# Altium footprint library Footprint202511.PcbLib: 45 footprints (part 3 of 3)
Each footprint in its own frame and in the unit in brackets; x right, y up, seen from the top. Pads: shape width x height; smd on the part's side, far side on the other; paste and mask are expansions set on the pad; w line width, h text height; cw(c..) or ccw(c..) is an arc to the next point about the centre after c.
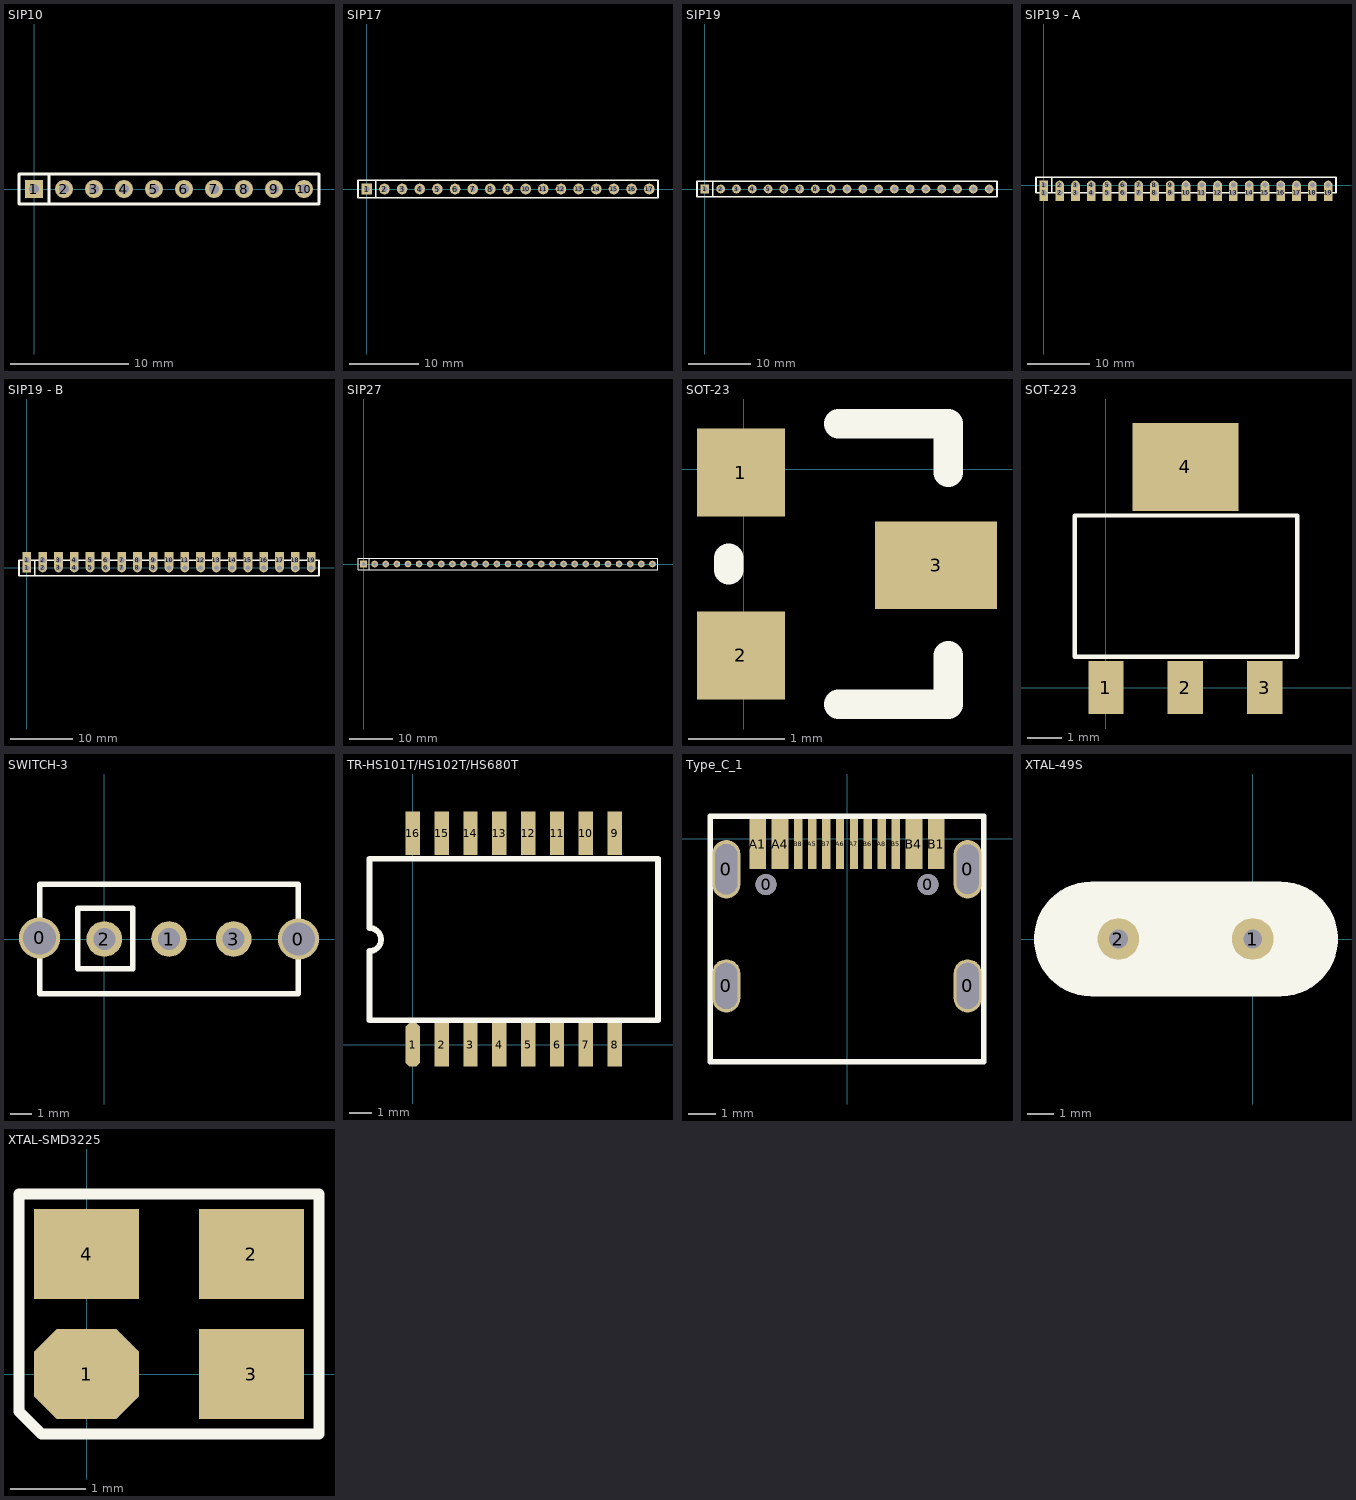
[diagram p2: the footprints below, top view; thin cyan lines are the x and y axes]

## SIP10 [mil]
pads (10):
  rect 60x60 hole 32: 1(0,0)
  round 60 hole 32: 2(100,0) 3(200,0) 4(300,0) 5(400,0) 6(500,0) 7(600,0) 8(700,0) 9(800,0) 10(900,0)
Top Overlay:
  lines w10: 50,-50 50,50 ; 950,-50 -50,-50 -50,50 950,50 950,-45

## SIP17 [mil]
height 43.31
pads (17):
  rect 60x60 hole 32: 1(0,0)
  round 60 hole 32: 2(100,0) 3(200,0) 4(300,0) 5(400,0) 6(500,0) 7(600,0) 8(700,0) 9(800,0) 10(900,0) 11(1000,0) 12(1100,0) 13(1200,0) 14(1300,0) 15(1400,0) 16(1500,0) 17(1600,0)
Top Overlay:
  lines w10: 50,-50 50,50 ; -50,-50 -50,50 1650,50 1650,-50 -50,-50

## SIP19 [mil]
height 43.31
pads (19):
  rect 55x55 hole 32: 1(0,0)
  round 55 hole 32: 2(100,0) 3(200,0) 4(300,0) 5(400,0) 6(500,0) 7(600,0) 8(700,0) 9(800,0) 10(900,0) 11(1000,0) 12(1100,0) 13(1200,0) 14(1300,0) 15(1400,0) 16(1500,0) 17(1600,0) 18(1700,0) 19(1800,0)
Top Overlay:
  lines w10: 50,-50 50,50 ; -50,-50 1850,-50 1850,50 -50,50 -50,-50

## SIP19 - A [mil]
height 43.31
pads (38):
  rect 55x100 hole 32: 1(0,-50) 2(100,-50) 3(200,-50)
  rect 55x55 hole 32: 1(0,0)
  round 55 hole 32: 2(100,0) 3(200,0) 4(300,0) 5(400,0) 6(500,0) 7(600,0) 8(700,0) 9(800,0) 10(900,0) 11(1000,0) 12(1100,0) 13(1200,0) 14(1300,0) 15(1400,0) 16(1500,0) 17(1600,0) 18(1700,0) 19(1800,0)
  rect 55x100 hole 32 unplated: 4(300,-50) 5(400,-50) 6(500,-50) 7(600,-50) 8(700,-50) 9(800,-50) 10(900,-50) 11(1000,-50) 12(1100,-50) 13(1200,-50) 14(1300,-50) 15(1400,-50) 16(1500,-50) 17(1600,-50) 18(1700,-50) 19(1800,-50)
Top Overlay:
  lines w10: 50,-50 50,50 ; -50,-50 -50,50 1850,50 1850,-50 -50,-50

## SIP19 - B [mil]
height 43.31
pads (38):
  rect 55x55 hole 32: 1(0,0)
  rect 55x100 hole 32: 1(0,50) 2(100,50) 3(200,50)
  round 55 hole 32: 2(100,0) 3(200,0) 4(300,0) 5(400,0) 6(500,0) 7(600,0) 8(700,0) 9(800,0) 10(900,0) 11(1000,0) 12(1100,0) 13(1200,0) 14(1300,0) 15(1400,0) 16(1500,0) 17(1600,0) 18(1700,0) 19(1800,0)
  rect 55x100 hole 32 unplated: 4(300,50) 5(400,50) 6(500,50) 7(600,50) 8(700,50) 9(800,50) 10(900,50) 11(1000,50) 12(1100,50) 13(1200,50) 14(1300,50) 15(1400,50) 16(1500,50) 17(1600,50) 18(1700,50) 19(1800,50)
Top Overlay:
  lines w10: 50,-50 50,50 ; -50,-50 -50,50 1850,50 1850,-50 -50,-50

## SIP27 [mil]
height 43.31
pads (27):
  rect 60x60 hole 32: 1(0,0)
  round 60 hole 32: 2(100,0) 3(200,0) 4(300,0) 5(400,0) 6(500,0) 7(600,0) 8(700,0) 9(800,0) 10(900,0) 11(1000,0) 12(1100,0) 13(1200,0) 14(1300,0) 15(1400,0) 16(1500,0) 17(1600,0) 18(1700,0) 19(1800,0) 20(1900,0) 21(2000,0) 22(2100,0) 23(2200,0) 24(2300,0) 25(2400,0) 26(2500,0) 27(2600,0)
Top Overlay:
  lines w10: 50,-50 50,50 ; -50,-50 2650,-50 2650,50 -50,50 -50,-50

## SOT-23 [mil]
height 43.31
pads (3):
  rect 36x36 smd: 1(-1.26,-1.37) 2(-1.26,-76.37)
  rect 50x36 smd: 3(78.74,-39.37)
Top Overlay:
  lines w12: -6.26,-41.37 -6.26,-36.37 ; 38.74,-96.37 83.74,-96.37 83.74,-76.37 ; 38.74,18.63 83.74,18.63 83.74,-1.37

## SOT-223 [mil]
height 43.31
pads (4):
  rect 40x60 smd: 1(0,0) 2(90,0) 3(180,0)
  rect 120x100 smd: 4(90,250)
Top Overlay:
  lines w5: -35.43,35 -35.43,194.57 -35,195 216.97,195 216.97,35.43 216.54,35 -35.43,35

## SWITCH-3 [mil]
height 21.65
pads (5):
  round 75 hole 60: 0(-118,2) 0(354,0)
  round 65 hole 40: 1(118,0) 2(0,0) 3(236,0)
Top Overlay:
  lines w10: -118,-100 -118,100 354,100 354,-100 -118,-100 ; -48,-54 -48,56 52,56 52,-54 -48,-54

## TR-HS101T/HS102T/HS680T [mm]
pads (16):
  oct 0.635x1.905 smd: 1(0,0)
  rect 0.635x1.905 smd: 2(1.27,0) 3(2.54,0) 4(3.81,0) 5(5.08,0) 6(6.35,0) 7(7.62,0) 8(8.89,0) 9(8.89,9.3) 10(7.62,9.3) 11(6.35,9.3) 12(5.08,9.3) 13(3.81,9.3) 14(2.54,9.3) 15(1.27,9.3) 16(0,9.3)
Top Overlay:
  lines w0.254: -1.905,1.07 -1.905,4.118 ccw(c-1.905,4.626) -1.905,5.134 -1.905,8.182 10.795,8.182 10.795,1.07 -1.905,1.07

## Type_C_1 [mm]
pads (18):
  oval 1x1.9 hole 0.8 slot 1.651 at 90 deg: 0(-4.325,-5.28) 0(4.325,-5.28)
  oval 1x2.1 hole 0.8 slot 1.803 at 90 deg: 0(-4.325,-1.1)
  round 0.75 hole 0.75: 0(-2.9,-1.65) 0(2.9,-1.65)
  oval 1x2.1 hole 0.8 slot 1.778 at 90 deg: 0(4.325,-1.1)
  rect 0.6x1.8 smd: A1(-3.2,-0.2) A4(-2.4,-0.2) B1(3.2,-0.2) B4(2.4,-0.2)
  rect 0.3x1.8 smd: A5(-1.25,-0.2) A6(-0.25,-0.2) A7(0.25,-0.2) A8(1.25,-0.2) B5(1.75,-0.2) B6(0.75,-0.2) B7(-0.75,-0.2) B8(-1.75,-0.2)
Top Overlay:
  lines w0.2: -4.9,-8 -4.9,0.8 4.9,0.8 4.9,-8 -4.9,-8

## XTAL-49S [mil]
pads (2):
  round 62 hole 28: 1(0,0) 2(-200,0)
Top Overlay:
  region: 87.98,71 76.98,71 76.98,-70 87.98,-70
  region: 78.98,75 68.98,75 68.98,-75 78.98,-75
  region: 69.98,81 57.98,81 57.98,-78 69.98,-78
  region: 58,81 41.34,81 41.34,-82.68 58,-82.68
  region: 41.34,82.68 -240,82.68 -240,-82.68 41.34,-82.68
  region: -240.02,80 -259.02,80 -259.02,-82.67 -240.02,-82.67
  region: -253.02,79 -273.02,79 -273.02,-78 -253.02,-78
  region: -264.02,74 -280.02,74 -280.02,-73 -264.02,-73
  lines w6: -240,-82.68 cw(c-240,0) -240,82.68 41.34,82.68 cw(c41.34,0) 41.34,-82.68 -240,-82.68
  lines w10: -317,-24 -317,23 -311,29 -311,-37 -308,-40 -308,43 -302,49 -302,-46 -298,-50 -298,54 -294,58 -294,-55 -289,-60 -289,57 -290,58 -290,59 -283,66 -283,-61 ; 88,-60 90,-58 90,63 91,63 97,57 97,-54 96,-55 100,-51 100,49 111,38 106,33 106,-43 112,-37 112,-33 112,30 118,24 118,-25 ; -283,-61 -280,-64 -283,-61

## XTAL-SMD3225 [mm]
pads (4):
  oct 1.4x1.2 smd: 1(0,0)
  rect 1.4x1.2 smd: 2(2.2,1.6) 3(2.2,0) 4(0,1.6)
Top Overlay:
  lines w0.152: -0.9,-0.5 -0.6,-0.8 3.1,-0.8 3.1,2.4 -0.9,2.4 -0.9,-0.5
